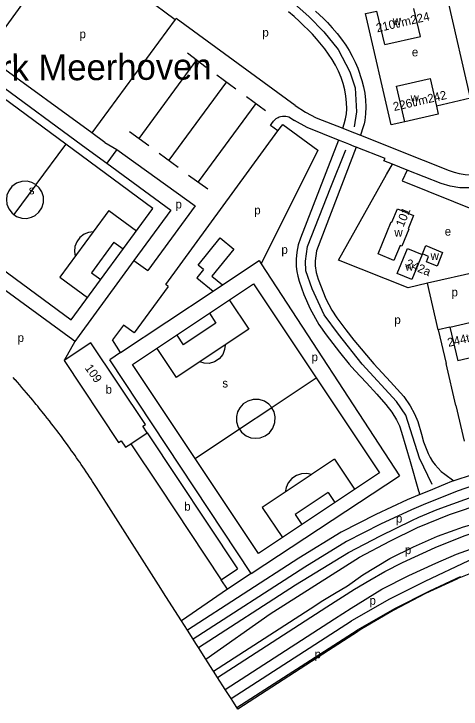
# Model space of a CAD drawing. Extents: x 155696 to 157795, y 382328 to 384028.
# Drawn here: x 156412.1 to 156619.5, y 382817.4 to 383139.6 of the extents above; entities that cross this region are included whole.
import ezdxf

# ---------------------------------------------------------------- set-up
doc = ezdxf.new("R2010")
doc.units = 0
for name, color, linetype in [('BLT_Basislijn', 7, 'Continuous'), ('BLT_Bebouwing', 7, 'Continuous'), ('BLT_Centroide', 7, 'Continuous'), ('BLT_Gemeentegrens', 7, 'Continuous'), ('BLT_Huisnummer', 7, 'Continuous'), ('BLT_Huisnummer_reeks', 7, 'Continuous'), ('BLT_Onderverdeling_panden', 7, 'Continuous'), ('BLT_Sport_parknaam', 7, 'Continuous'), ('BLT_Vlakafsluiter', 7, 'Continuous')]:
    doc.layers.add(name, color=color, linetype=linetype)

msp = doc.modelspace()

# ---------------------------------------------------------------- linework, layer by layer
at = {"layer": 'BLT_Basislijn'}
for p, q in [((156398.84, 383120.42), (156437.42, 383173.47)), ((156463.33, 383154.47), (156486.97, 383137.01)), ((156486.97, 383137.01), (156448.24, 383084.39)), ((156448.24, 383084.39), (156398.84, 383120.42)), ((156492.56, 383121.55), (156501.32, 383114.93)), ((156470.23, 383081.82), (156496.94, 383118.24)), ((156394.72, 383114.76), (156443.98, 383078.61)), ((156506.28, 383111.36), (156515.04, 383104.85)), ((156510.66, 383108.11), (156483.94, 383071.76)), ((156519.93, 383101.29), (156528.83, 383094.82)), ((156524.38, 383098.06), (156497.62, 383061.69)), ((156534.58, 383085.3), (156536.83, 383088.35)), ((156536.83, 383088.35), (156553.04, 383076.41)), ((156454.29, 383079.94), (156448.24, 383084.39)), ((156465.79, 383085.05), (156474.68, 383078.59)), ((156482.52, 383014.2), (156534.58, 383085.3)), ((156436.01, 383079.1), (156422.35, 383060.5)), ((156459.86, 383076.75), (156455.18, 383070.39)), ((156459.86, 383076.75), (156496.21, 383050.57)), ((156479.52, 383075.01), (156488.36, 383068.52)), ((156553.04, 383076.41), (156526.84, 383023.75)), ((156584.95, 383065.11), (156587.65, 383069.91)), ((156594.52, 383067.19), (156587.65, 383069.91)), ((156493.16, 383064.9), (156502.07, 383058.49)), ((156422.24, 383060.35), (156412.14, 383046.58)), ((156496.21, 383050.57), (156474.22, 383020.66)), ((156456.12, 383048.47), (156448.89, 383038.63)), ((156456.12, 383048.47), (156469, 383039.02)), ((156448.83, 383038.55), (156433.41, 383017.54)), ((156497.52, 383023.13), (156507.71, 383035.79)), ((156507.71, 383035.79), (156514.15, 383030.58)), ((156458.53, 383033.77), (156448.11, 383019.57)), ((156458.53, 383033.77), (156462.83, 383030.62)), ((156514.15, 383030.58), (156503.92, 383017.97)), ((156467.81, 383025.28), (156474.22, 383020.66)), ((156500, 383021.15), (156497.52, 383023.13)), ((156508.85, 383013.97), (156525.86, 383025.24)), ((156525.86, 383025.24), (156526.84, 383023.75)), ((156526.84, 383023.75), (156590.87, 382925.53)), ((156629.86, 383020.68), (156603.98, 383014.7)), ((156433.41, 383017.54), (156446.29, 383008.09)), ((156448.11, 383019.57), (156452.41, 383016.41)), ((156503.92, 383017.97), (156508.85, 383013.97)), ((156483.67, 383013.29), (156482.52, 383014.2)), ((156504.48, 383011.07), (156508.85, 383013.97)), ((156608.92, 382993.13), (156603.98, 383014.7)), ((156461.6, 382982.66), (156504.48, 383011.07)), ((156511.97, 383007), (156521.03, 382993.42)), ((156502.8, 383000.87), (156505.84, 382996.31)), ((156505.84, 382996.31), (156490.66, 382986.18)), ((156614.32, 382994.38), (156608.92, 382993.13)), ((156487.61, 382990.74), (156490.66, 382986.18)), ((156521.03, 382993.42), (156510.09, 382986.12)), ((156608.92, 382993.13), (156612.52, 382977.56)), ((156440.34, 382987.8), (156435.43, 382978.91)), ((156461.6, 382982.66), (156457.81, 382988.48)), ((156478.37, 382984.57), (156487.42, 382971)), ((156509.99, 382986.06), (156487.42, 382971)), ((156461.6, 382982.66), (156456.57, 382979.3)), ((156552.36, 382970.79), (156531.83, 382957.09)), ((156531.66, 382956.98), (156516.79, 382947.05)), ((156617.03, 382958.03), (156620.85, 382941.49)), ((156516.79, 382947.05), (156496.25, 382933.35)), ((156560.76, 382933.16), (156550.12, 382926.06)), ((156560.76, 382933.16), (156570.05, 382919.23)), ((156522.1, 382880.15), (156590.87, 382925.53)), ((156550.03, 382926), (156527.32, 382910.85)), ((156557.87, 382917.82), (156542.51, 382907.58)), ((156557.87, 382917.82), (156560.97, 382913.18)), ((156527.32, 382910.85), (156536.61, 382896.93)), ((156542.51, 382907.58), (156545.62, 382902.93)), ((156619.14, 382878.33), (156619, 382878.75)), ((156511.2, 382872.92), (156489.81, 382858.31)), ((156571.27, 382853.96), (156571.58, 382853.3))]:
    msp.add_line(p, q, dxfattribs=at)
for points in [[(156497.22, 383249.89), (156501.44, 383243.93), (156515.58, 383226.8), (156518.56, 383221.84), (156521.04, 383215.63), (156521.46, 383210.22), (156520.9, 383195.67), (156520.71, 383186.53), (156522.58, 383176.27), (156526.87, 383164.89), (156532.84, 383154.44), (156540.85, 383145.49), (156548.87, 383138.4), (156555.77, 383131.31), (156562.49, 383123.1), (156567.89, 383112.65), (156570.32, 383105.37), (156571.06, 383094.18), (156569.95, 383087.28)], [(156623.9, 383100.44), (156613.46, 383145.65)], [(156564.61, 383086.6), (156565.3, 383088.66), (156565.88, 383090.92), (156566.28, 383093.23), (156566.47, 383095.57), (156566.43, 383098.53), (156566.11, 383101.47), (156565.56, 383104.37), (156564.82, 383107.24), (156563.84, 383110.16), (156562.62, 383112.99), (156561.22, 383115.74), (156559.7, 383118.43), (156558.07, 383120.96), (156556.27, 383123.39), (156552.44, 383128.04), (156550.57, 383130.13), (156548.62, 383132.14), (156546.62, 383134.1), (156544.6, 383136.05), (156542.08, 383138.35), (156539.45, 383140.52)], [(156551.92, 383140.87), (156555.71, 383137.42), (156557.51, 383135.59), (156559.77, 383133.1), (156561.97, 383130.55), (156564.06, 383127.9), (156565.99, 383125.14), (156567.58, 383122.57), (156569.04, 383119.92), (156570.37, 383117.21), (156571.55, 383114.42), (156573.53, 383108.7), (156574.28, 383105.77), (156574.81, 383102.78), (156575.14, 383099.64), (156575.27, 383096.48), (156575.18, 383093.32), (156574.87, 383090.18), (156574.58, 383088.66), (156574.15, 383087.18), (156572.82, 383083.33)], [(156593.37, 383089.5), (156587, 383088.09), (156575.14, 383139.74), (156580.43, 383140.9)], [(156542.6, 383097.08), (156487.33, 383137.5), (156486.97, 383137.01)], [(156623.9, 383100.44), (156608.07, 383096.79)], [(156542.6, 383097.08), (156547.33, 383094.01), (156552.36, 383091.47), (156564.61, 383086.6)], [(156534.58, 383085.3), (156531.12, 383087.8), (156531.81, 383088.82), (156532.45, 383089.83), (156533.08, 383090.54), (156533.79, 383091.13), (156534.62, 383091.61), (156535.12, 383091.81), (156535.82, 383092.05), (156536.71, 383092.23), (156537.48, 383092.21), (156538.23, 383092.19), (156539.02, 383092.02), (156539.58, 383091.81), (156542.21, 383090.22)], [(156562.61, 383081.1), (156548.05, 383086.92), (156542.21, 383090.22)], [(156564.61, 383086.6), (156568, 383085.25)], [(156568, 383085.25), (156570.04, 383084.44)], [(156570.04, 383084.44), (156572.82, 383083.33)], [(156562.61, 383081.1), (156545.01, 383035.67), (156543.99, 383032.49), (156543.37, 383029.21), (156543.07, 383025.88), (156543.05, 383022.54), (156543.27, 383020.24), (156543.74, 383017.97), (156544.38, 383015.75), (156546.52, 383009.58), (156549.52, 383002.81), (156553.52, 382995.61), (156556.95, 382990.82), (156563.07, 382982.77), (156567.63, 382977.24), (156570.23, 382974.28), (156575.63, 382968.51), (156580.39, 382963.26), (156584.58, 382958.61), (156587.37, 382955.03), (156589.61, 382951.48), (156590.89, 382948.65), (156591.87, 382945.71), (156595.83, 382932.09), (156599.79, 382918.46), (156600, 382917.75), (156600.02, 382917.01), (156599.98, 382916.64)], [(156565.89, 383079.79), (156562.61, 383081.1)], [(156572.82, 383083.33), (156584.15, 383078.83), (156589.8, 383076.59)], [(156443.98, 383078.61), (156455.18, 383070.39)], [(156570.82, 383077.82), (156552.42, 383029.79), (156551.84, 383025.17), (156551.85, 383022.84), (156552.35, 383019.7), (156553.27, 383016.65), (156556.8, 383007.51), (156559.62, 383002.25), (156561.94, 382998.75), (156566, 382993.19), (156569.71, 382988.33), (156579.06, 382977.45), (156586.71, 382969.1), (156592.92, 382962.19), (156595.89, 382957.87), (156597.91, 382954.17), (156599.39, 382950.6), (156601.17, 382944.85), (156602.07, 382941.3), (156604.22, 382935.77), (156605.14, 382933.94), (156606.22, 382932.2), (156607.47, 382930.54), (156610.32, 382927.51), (156611.92, 382926.18), (156616.08, 382923.15)], [(156567.49, 383079.15), (156565.89, 383079.79)], [(156570.82, 383077.82), (156569.93, 383078.17), (156567.49, 383079.15)], [(156587.65, 383069.91), (156583.63, 383071.5), (156584.32, 383072.49), (156570.82, 383077.82)], [(156606.12, 382921.48), (156600.15, 382933.6), (156593.81, 382953.56), (156589.52, 382959.91), (156573.67, 382977.26), (156562.67, 382991.06), (156555.96, 383000.02), (156550.36, 383012.15), (156547.57, 383020.54), (156547.4, 383024.92), (156548.33, 383031.83), (156559.15, 383059.25), (156566.05, 383076.6)], [(156589.8, 383076.59), (156614, 383067.01)], [(156614, 383067.01), (156616.23, 383066.23), (156618.6, 383065.64), (156621.37, 383065.15), (156624.45, 383064.91), (156625.43, 383064.97), (156626.46, 383065.19), (156627.33, 383065.58), (156628.72, 383066.54), (156629.65, 383067.65), (156630.34, 383069.05), (156630.63, 383070.54), (156630.46, 383072.04)], [(156455.18, 383070.39), (156484.93, 383048.58), (156467.81, 383025.28)], [(156603.98, 383014.7), (156594.99, 383012.62), (156562.66, 383025.47), (156584.95, 383065.11)], [(156594.52, 383067.19), (156592.24, 383062.18), (156627.84, 383047.86), (156633.13, 383024.93)], [(156634.74, 383053.52), (156634.01, 383056.17), (156633.49, 383057.06), (156632.92, 383057.73), (156632.27, 383058.37), (156631.44, 383058.9), (156630.5, 383059.32), (156629.59, 383059.55), (156628.71, 383059.64), (156627.33, 383059.52), (156624.27, 383059.03), (156618.84, 383058.91), (156614.37, 383059.7), (156610.18, 383060.99), (156594.52, 383067.19)], [(156422.21, 383060.48), (156420.48, 383061.42), (156418.24, 383061.98), (156415.76, 383061.9), (156413.31, 383061.07), (156411.24, 383059.57), (156409.76, 383057.64), (156408.92, 383055.57), (156408.65, 383053.57), (156408.87, 383051.43), (156409.73, 383049.21), (156411.27, 383047.2), (156412.14, 383046.58)], [(156412.14, 383046.58), (156413.37, 383045.7), (156415.77, 383044.9), (156418.14, 383044.81), (156420.24, 383045.29), (156422.04, 383046.2), (156423.73, 383047.66), (156425.08, 383049.69), (156425.82, 383052.14), (156425.82, 383054.72), (156425.09, 383057.09), (156423.83, 383059.03), (156422.37, 383060.36)], [(156440.34, 382987.8), (156439.42, 382988.47), (156350.17, 383053.65), (156351.43, 383055.23)], [(156448.86, 383038.59), (156446.78, 383038.33), (156444.65, 383037.48), (156442.72, 383036), (156441.25, 383034), (156440.42, 383031.71), (156440.25, 383029.42), (156440.62, 383027.36)], [(156467.81, 383025.28), (156442.35, 382990.58), (156440.34, 382987.8)], [(156500, 383021.15), (156496.89, 383017.24), (156504.48, 383011.07)], [(156483.67, 383013.29), (156467.88, 382991.77), (156462.96, 382995.38), (156457.81, 382988.48)], [(156510.04, 382986.09), (156509.84, 382983.96), (156508.98, 382981.73), (156507.39, 382979.72), (156505.21, 382978.26), (156502.74, 382977.57), (156500.35, 382977.63), (156498.3, 382978.26)], [(156522.1, 382880.15), (156456.57, 382979.3)], [(156617.03, 382958.03), (156612.52, 382977.56)], [(156531.68, 382957.12), (156530.32, 382958.67), (156528.31, 382960.02), (156525.84, 382960.83), (156523.14, 382960.89), (156520.56, 382960.16), (156518.41, 382958.78), (156516.84, 382957.05), (156515.86, 382955.18), (156515.31, 382952.99), (156515.36, 382950.5), (156516.16, 382947.97), (156516.79, 382947.05)], [(156516.79, 382947.05), (156517.69, 382945.74), (156519.76, 382944.09), (156522.07, 382943.15), (156524.3, 382942.87), (156526.4, 382943.12), (156528.58, 382943.96), (156530.64, 382945.47), (156532.25, 382947.61), (156533.17, 382950.16), (156533.3, 382952.76), (156532.76, 382955.11), (156531.8, 382956.95)], [(156550.07, 382926.03), (156547.93, 382926.52), (156545.53, 382926.44), (156543.1, 382925.68), (156540.94, 382924.24), (156539.3, 382922.28), (156538.31, 382920.1), (156537.94, 382917.93)], [(156639.84, 382920.39), (156638.61, 382924.33), (156634.03, 382923.62), (156626.19, 382921.26), (156617.67, 382918.41), (156601.87, 382912.01)], [(156616.08, 382923.15), (156615, 382922.79), (156612.13, 382921.61)], [(156624.6, 382926.01), (156616.08, 382923.15)], [(156497.68, 382845.97), (156542.77, 382875.03), (156567.23, 382889.96), (156582.06, 382897.69), (156596.57, 382904.83), (156599.84, 382906.27), (156608.43, 382909.87), (156628.53, 382917.16), (156639.46, 382920.3), (156639.84, 382920.39)], [(156612.13, 382921.61), (156604.3, 382918.41)], [(156599.98, 382916.64), (156594.41, 382914.36), (156579.92, 382907.54), (156563.86, 382899.38), (156544.29, 382887.31), (156492.57, 382853.98)], [(156501.18, 382840.49), (156531.01, 382861.48), (156572.31, 382887.78), (156586.45, 382895.27), (156599.34, 382901.57), (156614.18, 382907.59), (156630.22, 382912.94), (156652.19, 382917.54)], [(156604.3, 382918.41), (156599.98, 382916.64)], [(156601.87, 382912.01), (156596.43, 382909.78), (156582.12, 382903.05), (156566.3, 382895.02), (156546.96, 382883.08), (156495.26, 382849.77)], [(156566.76, 382874.58), (156573.92, 382879.64), (156586.48, 382887.13), (156597.4, 382892.64), (156608.61, 382897.47), (156620.61, 382901.79), (156633.97, 382905.61), (156646.1, 382908.23), (156659.72, 382910.25)], [(156506.56, 382832.05), (156557.2, 382864.7), (156570.07, 382872.91), (156577.18, 382877.12), (156584.12, 382881.12), (156592.38, 382885.26), (156607.52, 382892.27), (156620.88, 382897.68), (156634.38, 382902.1), (156647.44, 382905.78)], [(156510.11, 382826.5), (156560.78, 382859.16), (156568.46, 382864.1), (156582.79, 382872.89), (156595.26, 382879.27), (156607.85, 382884.98), (156617.39, 382889.11), (156630.83, 382893.92), (156641.39, 382897.27), (156643.3, 382897.78)], [(156643.3, 382897.78), (156644.19, 382894.46), (156638.26, 382892.4), (156622.98, 382886.14), (156602.6, 382876.58)], [(156522.1, 382880.15), (156511.2, 382872.92)], [(156619, 382878.75), (156604.8, 382872.09)], [(156511.2, 382872.92), (156508.29, 382877.3)], [(156602.6, 382876.58), (156586.31, 382868.3), (156568.68, 382858.23)], [(156504.67, 382835.01), (156549.5, 382863.9), (156555.31, 382867.65), (156560.79, 382871.02), (156566.76, 382874.58)], [(156604.8, 382872.09), (156588.68, 382863.9), (156571.27, 382853.96)], [(156512.8, 382822.28), (156512.85, 382822.32), (156568.68, 382858.23)], [(156515.48, 382818.06), (156515.57, 382818.12), (156571.27, 382853.96)]]:
    msp.add_lwpolyline(points, dxfattribs=at)
for points in [[(156357.73, 383057.45), (156438.71, 382997.82), (156476.63, 383049.33), (156395.65, 383108.95)], [(156523.2, 383014.5), (156581.62, 382926.94), (156525.5, 382889.5), (156467.08, 382977.06)]]:
    msp.add_lwpolyline(points, close=True, dxfattribs=at)
at = {"layer": 'BLT_Bebouwing'}
for p, q in [((156584.1, 383125.38), (156580.43, 383140.9)), ((156593.37, 383089.5), (156589.52, 383106.04)), ((156614.32, 382994.38), (156617.91, 382978.81)), ((156473.86, 382945.48), (156515.84, 382882.32)), ((156466.36, 382940.39), (156479.42, 382920.75)), ((156479.42, 382920.75), (156508.29, 382877.3)), ((156508.29, 382877.3), (156515.84, 382882.32))]:
    msp.add_line(p, q, dxfattribs=at)
for points in [[(156584.1, 383125.38), (156600.59, 383129.16), (156597.63, 383142)], [(156589.52, 383106.04), (156605.1, 383109.63), (156608.07, 383096.79)], [(156608.07, 383096.79), (156608.93, 383093.09), (156593.37, 383089.5)], [(156614.32, 382994.38), (156630.84, 382998.19), (156631.47, 382995.47)], [(156631.47, 382995.47), (156634.44, 382982.62), (156617.91, 382978.81)], [(156473.86, 382945.48), (156471.89, 382948.47), (156473.14, 382949.31), (156447.87, 382987.12), (156435.43, 382978.91)], [(156435.43, 382978.91), (156460.58, 382940.94), (156461.81, 382941.76), (156463.81, 382938.7), (156466.36, 382940.39)]]:
    msp.add_lwpolyline(points, dxfattribs=at)
for points in [[(156590.02, 383049.2), (156597.47, 383046.1), (156594.91, 383039.93), (156595.19, 383039.82), (156591.96, 383031.96), (156591.19, 383032.26), (156588.33, 383025.34), (156581.01, 383028.41), (156587.08, 383043.14), (156587.44, 383042.99)], [(156594.67, 383030.87), (156601.41, 383028.06), (156596.57, 383016.44), (156589.84, 383019.22)], [(156603.09, 383032.18), (156610.9, 383029.02), (156608.34, 383022.66), (156603.39, 383024.66), (156604.35, 383027.19), (156601.53, 383028.33)]]:
    msp.add_lwpolyline(points, close=True, dxfattribs=at)
at = {"layer": 'BLT_Gemeentegrens'}
msp.add_line((156495.26, 382849.77), (156492.57, 382853.98), dxfattribs=at)
for points in [[(156489.81, 382858.31), (156482.62, 382869.59), (156479.19, 382874.96), (156458.3, 382907.71), (156450.46, 382920), (156450.14, 382920.5), (156449.81, 382921.01), (156449.22, 382921.92), (156448.63, 382922.83), (156447.9, 382923.96), (156447.16, 382925.09), (156446.39, 382926.24), (156445.62, 382927.4), (156444.85, 382928.54), (156444.08, 382929.68), (156443.38, 382930.71), (156442.67, 382931.74), (156441.94, 382932.79), (156441.21, 382933.84), (156440.48, 382934.89), (156439.74, 382935.93), (156438.92, 382937.09), (156438.1, 382938.24), (156437.29, 382939.36), (156436.48, 382940.48), (156435.46, 382941.86), (156434.45, 382943.24), (156433.68, 382944.27), (156432.91, 382945.29), (156432.14, 382946.32), (156431.36, 382947.34), (156430.48, 382948.49), (156429.6, 382949.63), (156428.59, 382950.94), (156427.57, 382952.24), (156426.94, 382953.04), (156426.74, 382953.29), (156425.92, 382954.33), (156425.22, 382955.19), (156424.53, 382956.06), (156423.85, 382956.89), (156423.17, 382957.72), (156422.49, 382958.55), (156421.81, 382959.38), (156420.87, 382960.52), (156419.92, 382961.65), (156418.95, 382962.81), (156417.98, 382963.95), (156416.93, 382965.18), (156415.89, 382966.4), (156414.82, 382967.62), (156413.75, 382968.85), (156412.82, 382969.9), (156412.8, 382969.93), (156411.84, 382971)], [(156619.14, 382878.33), (156618.35, 382878.01), (156617.46, 382877.6)], [(156625.33, 382880.86), (156619.14, 382878.33)], [(156617.46, 382877.6), (156603.02, 382870.9), (156588.05, 382863.06), (156573.47, 382854.52), (156571.58, 382853.3)], [(156492.57, 382853.98), (156489.81, 382858.31)], [(156571.58, 382853.3), (156571.49, 382853.25), (156558.05, 382844.57), (156515.92, 382817.38), (156515.48, 382818.06)], [(156497.68, 382845.97), (156496.57, 382847.71), (156495.26, 382849.77)], [(156501.18, 382840.49), (156497.68, 382845.97)], [(156504.67, 382835.01), (156504.41, 382835.42), (156501.18, 382840.49)], [(156506.56, 382832.05), (156504.67, 382835.01)], [(156510.11, 382826.5), (156506.56, 382832.05)], [(156512.8, 382822.28), (156510.11, 382826.5)], [(156515.48, 382818.06), (156513.63, 382820.98), (156512.8, 382822.28)]]:
    msp.add_lwpolyline(points, dxfattribs=at)
at = {"layer": 'BLT_Onderverdeling_panden'}
msp.add_line((156466.36, 382940.39), (156473.86, 382945.48), dxfattribs=at)
at = {"layer": 'BLT_Vlakafsluiter'}
msp.add_line((156454.29, 383079.94), (156459.86, 383076.75), dxfattribs=at)

# ---------------------------------------------------------------- texts
at = {"layer": 'BLT_Centroide'}
for s, p in [('w', (156587.83, 383134.41)), ('p', (156442.55, 383128.28)), ('p', (156527.34, 383129)), ('e', (156596.65, 383119.89)), ('w', (156596.05, 383098.81)), ('s', (156419.04, 383055.94)), ('p', (156487.04, 383049.4)), ('p', (156523.58, 383046.66)), ('w', (156588.55, 383036.29)), ('e', (156611.88, 383036.8)), ('p', (156536.16, 383028.37)), ('w', (156605.33, 383025.56)), ('w', (156593.58, 383020.62)), ('p', (156615.04, 383008.65)), ('p', (156588.54, 382995.83)), ('p', (156413.86, 382987.53)), ('p', (156550.16, 382978.6)), ('s', (156508.77, 382966.43)), ('b', (156454.64, 382963.55)), ('b', (156491.09, 382909.34)), ('p', (156589.27, 382903.82)), ('p', (156593.39, 382889.2)), ('p', (156577, 382865.74)), ('p', (156551.56, 382840.88))]:
    msp.add_text(s, height=4, dxfattribs=at).set_placement(p)
at = {"layer": 'BLT_Huisnummer'}
for s, rotation, p in [('101', 67.4204, (156592.72, 383040.49)), ('242a', 337.4204, (156593.45, 383022.48)), ('109', 305.7382, (156444.82, 382975.43))]:
    msp.add_text(s, height=4, rotation=rotation, dxfattribs=at).set_placement(p)
at = {"layer": 'BLT_Huisnummer_reeks'}
for s, rotation, p in [('210t/m224', 13.0091, (156580.61, 383130.98)), ('226t/m242', 13.0066, (156588.47, 383094.52)), ('244t/m258', 13.0091, (156613.62, 382985.21))]:
    msp.add_text(s, height=4, rotation=rotation, dxfattribs=at).set_placement(p)
at = {"layer": 'BLT_Sport_parknaam'}
msp.add_text('Sportpark Meerhoven', height=12, rotation=0.3414, dxfattribs=at).set_placement((156349.53, 383108.26))

doc.saveas('drawing.dxf')
